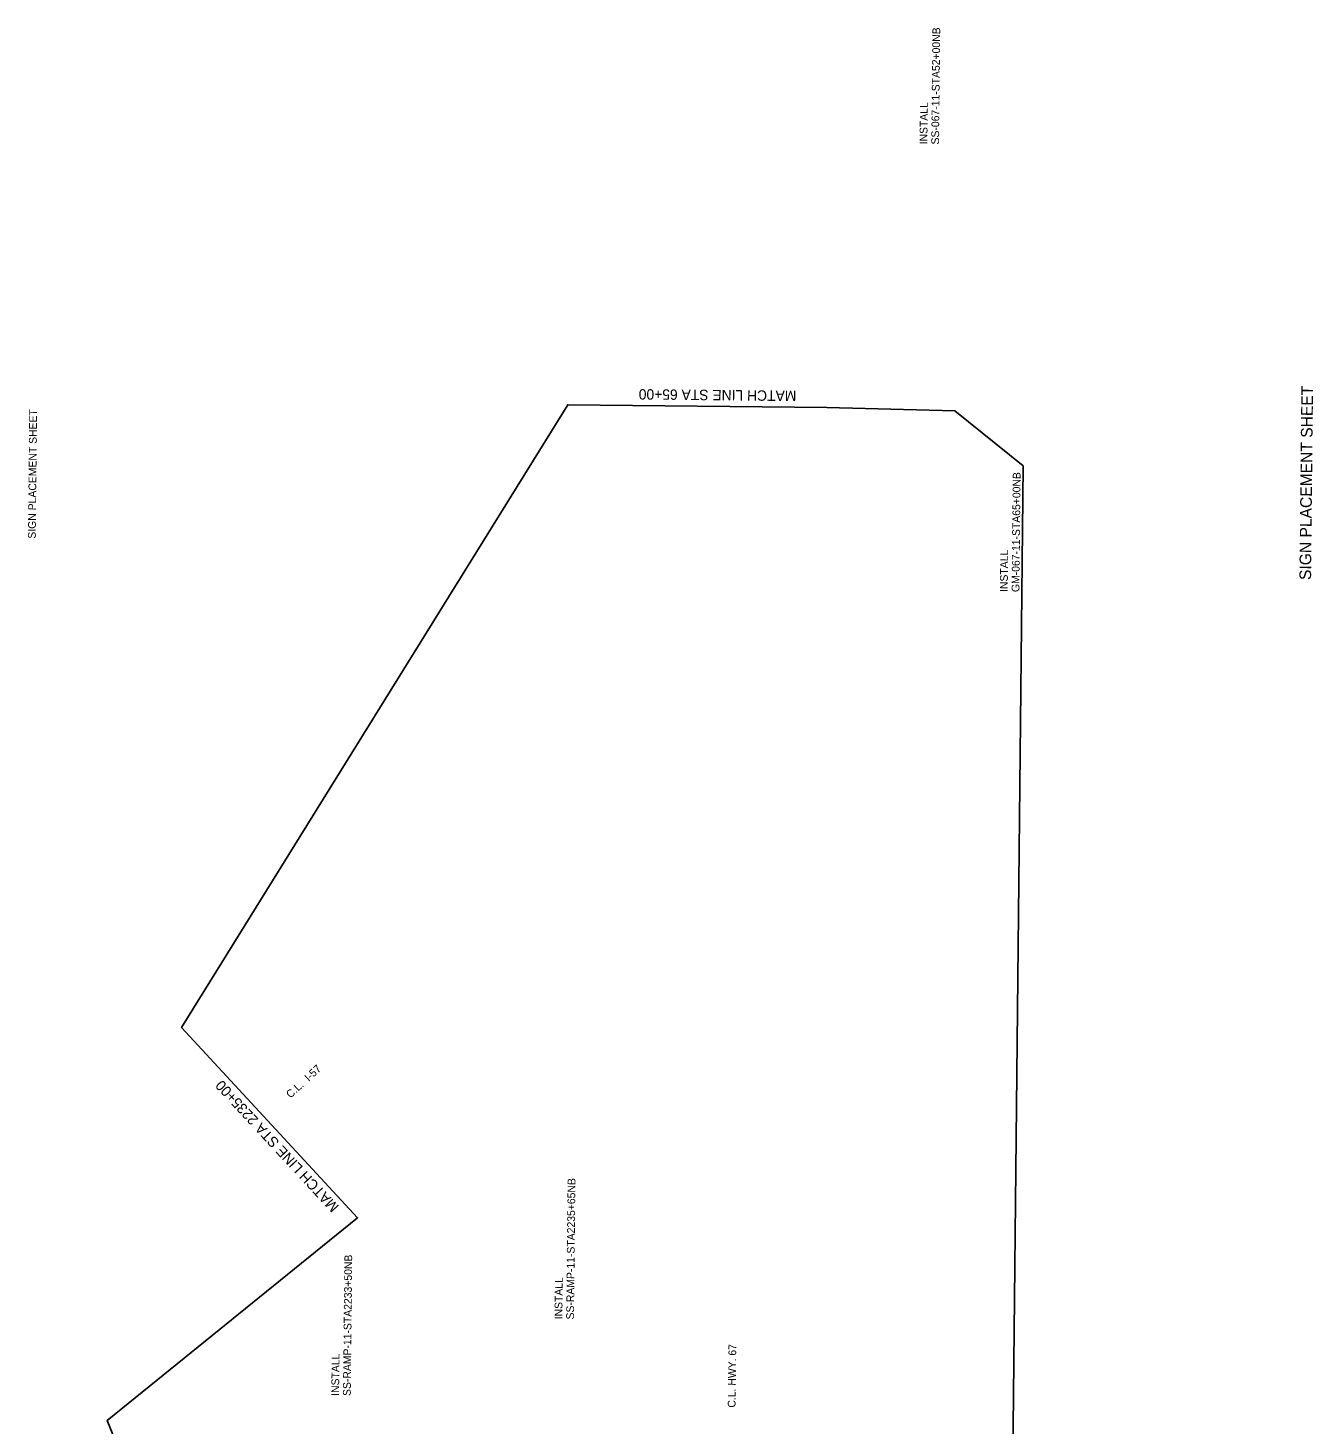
# Model space of a CAD drawing. Extents: x 1727808 to 1728800, y 771204 to 773048.
# Drawn here: x 1727808 to 1728800, y 771972 to 773048 of the extents above; entities that cross this region are included whole.
import ezdxf

# ---------------------------------------------------------------- set-up
doc = ezdxf.new("R2010")
doc.units = 0
for name, color, linetype in [('R_6IN_DASHED-RPM_WHITE_ENHANCED THERMO', 7, 'Continuous'), ('R_6IN_SOLID_WHITE_THERMOPLASTIC', 7, 'Continuous'), ('R_6IN_SOLID_YELLOW_ENHANCED THERMO', 7, 'Continuous'), ('R_8IN_SOLID_WHITE_THERMO', 7, 'Continuous'), ('R_RPM_TYPE 2_RED-WHITE', 7, 'Continuous'), ('R_WORDS_WHITE_THERMO', 7, 'Continuous')]:
    doc.layers.add(name, color=color, linetype=linetype)

msp = doc.modelspace()

# ---------------------------------------------------------------- linework, layer by layer
at = {"layer": 'R_8IN_SOLID_WHITE_THERMO'}
for p, q in [((1728424.7, 772755.7), (1728224.8, 772757.8)), ((1727926.9, 772277.6), (1728062.7, 772130.8))]:
    msp.add_line(p, q, dxfattribs=at)
at = {"layer": 'R_RPM_TYPE 2_RED-WHITE'}
msp.add_lwpolyline([(1728560.4, 771204), (1728053.5, 771210.3), (1727861.2, 771718.4), (1727954.5, 771739.6), (1727899.7, 771899.8), (1727869.5, 771974.4), (1728062.7, 772130.8), (1727926.9, 772277.6), (1728224.8, 772757.8), (1728424.7, 772755.7), (1728523.3, 772753), (1728576.2, 772710.6)], close=True, dxfattribs=at)

# ---------------------------------------------------------------- texts
at = {"layer": 'R_6IN_DASHED-RPM_WHITE_ENHANCED THERMO'}
for s, rotation, p in [('C.L.  I-57', 42.6023, (1728010.9, 772222.6)), ('C.L. HWY. 67', 89.2523, (1728354.2, 771984.3))]:
    msp.add_text(s, height=6, rotation=rotation, dxfattribs=at).set_placement(p)
at = {"layer": 'R_6IN_SOLID_WHITE_THERMOPLASTIC'}
msp.add_text('SIGN PLACEMENT SHEET', height=9, rotation=89.4, dxfattribs=at).set_placement((1728798.2, 772622.6))
at = {"layer": 'R_6IN_SOLID_YELLOW_ENHANCED THERMO'}
msp.add_text('SIGN PLACEMENT SHEET', height=6, rotation=89.4, dxfattribs=at).set_placement((1727814.4, 772654.5))
at = {"layer": 'R_8IN_SOLID_WHITE_THERMO'}
for s, rotation, p in [('MATCH LINE STA 65+00', 179.4, (1728401.2, 772768.6)), ('MATCH LINE STA 2235+00', 132.75, (1728048.8, 772139.6))]:
    msp.add_text(s, height=8, rotation=rotation, dxfattribs=at).set_placement(p)
at = {"layer": 'R_WORDS_WHITE_THERMO'}
for s, p in [('SS-067-11-STA52+00NB', (1728511.2, 772958.5)), ('INSTALL', (1728502.2, 772958.6)), ('GM-067-11-STA65+00NB', (1728573.2, 772613.3)), ('INSTALL', (1728564.2, 772613.4)), ('SS-RAMP-11-STA2235+65NB', (1728229.6, 772052.3)), ('SS-RAMP-11-STA2233+50NB', (1728057.4, 771993.3)), ('INSTALL', (1728220.6, 772052.4)), ('INSTALL', (1728048.4, 771993.4))]:
    msp.add_text(s, height=6, rotation=89.4, dxfattribs=at).set_placement(p)

doc.saveas('drawing.dxf')
